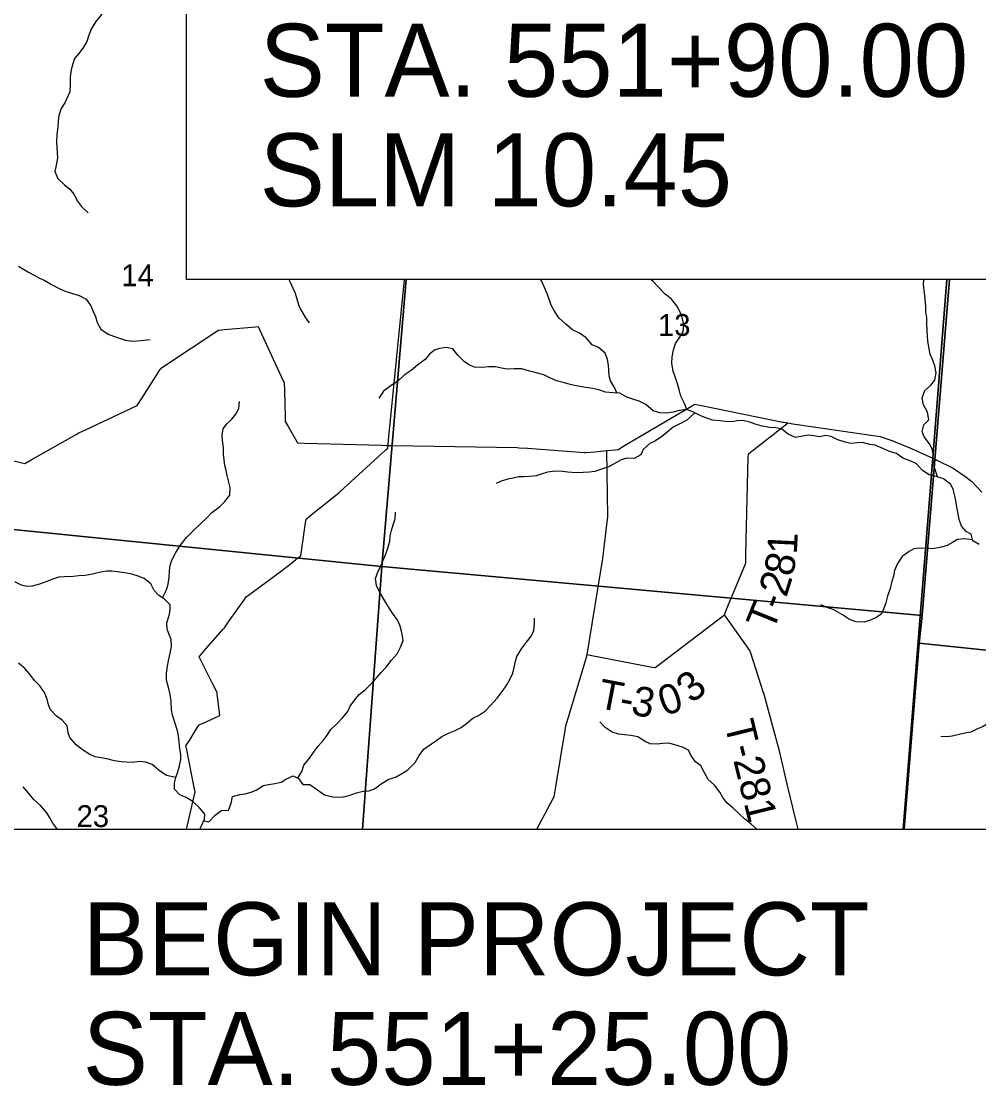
# Model space of a CAD drawing. Extents: x 0 to 34, y 0 to 22.
# Drawn here: x 24.339 to 26.174, y 16.062 to 18.118 of the extents above; entities that cross this region are included whole.
import ezdxf

# ---------------------------------------------------------------- set-up
doc = ezdxf.new("R2010")
doc.units = 0
for name, color, linetype in [('GM_X_Corporation', 7, 'Continuous'), ('GM_X_County_Road', 7, 'Continuous'), ('GM_X_Minor_River', 7, 'Continuous'), ('GM_X_Section_Text', 7, 'Continuous'), ('GM_X_Township_Road', 7, 'Continuous'), ('GM_X_Township_Road_Text', 7, 'Continuous'), ('SH_Data', 7, 'Continuous'), ('SH_Text', 7, 'Continuous')]:
    doc.layers.add(name, color=color, linetype=linetype)

msp = doc.modelspace()

# ---------------------------------------------------------------- linework, layer by layer
at = {"layer": 'GM_X_Corporation'}
for points in [[(25.0768, 17.6235), (25.0299, 17.0732), (24.0111, 17.1749), (24.0929, 18.2038), (24.656, 18.1575)], [(26.3421, 17.8905), (26.9688, 17.8482), (27.1442, 17.8319), (27.1132, 17.3107), (27.1145, 16.8163), (26.06, 16.9257), (26.0658, 16.9791), (26.1183, 17.6235)], [(26.1183, 17.6235), (26.0658, 16.9791), (25.0299, 17.0732), (25.0768, 17.6235)], [(26.1133, 17.6235), (26.0862, 17.2814), (26.0298, 16.5691)], [(26.0298, 16.5691), (26.0862, 17.2814), (26.1133, 17.6235)], [(24.3169, 16.1005), (23.9154, 16.1379), (24.0111, 17.1749), (25.0299, 17.0732), (24.993, 16.5691)], [(24.993, 16.5691), (25.0299, 17.0732), (26.0658, 16.9791), (26.06, 16.9257), (26.0314, 16.5691)], [(26.0314, 16.5691), (26.06, 16.9257), (27.1145, 16.8163), (27.112, 15.7689), (26.1924, 15.8415)]]:
    msp.add_lwpolyline(points, dxfattribs=at)
at = {"layer": 'GM_X_County_Road'}
msp.add_lwpolyline([(24.6557, 16.5691), (24.6569, 16.5743), (24.6703, 16.6329), (24.6721, 16.6408), (24.6698, 16.6525), (24.6562, 16.7213), (24.6547, 16.729), (24.6612, 16.7394), (24.677, 16.7649), (24.6797, 16.7692), (24.6933, 16.7754), (24.7116, 16.7837), (24.7199, 16.7875), (24.7185, 16.7983), (24.7147, 16.8281), (24.7142, 16.8315), (24.7068, 16.8463), (24.6798, 16.9), (24.6928, 16.9151), (24.7259, 16.9527), (24.7283, 16.9553), (24.7378, 16.9688), (24.7668, 17.0096), (24.7704, 17.0146), (24.7816, 17.0229), (24.838, 17.0646), (24.8413, 17.067), (24.8538, 17.0769), (24.8694, 17.0894), (24.8747, 17.0936), (24.8766, 17.1068), (24.8839, 17.1564), (24.8849, 17.1639), (24.8946, 17.1717), (24.9416, 17.2093), (24.9475, 17.214), (24.9567, 17.2224), (25.0381, 17.2967), (25.0416, 17.2999), (25.042, 17.3052), (25.0429, 17.3151), (25.0736, 17.6235)], dxfattribs=at)
at = {"layer": 'GM_X_Minor_River'}
for points in [[(24.547, 18.2577), (24.5353, 18.2481), (24.5356, 18.2375), (24.5378, 18.2261), (24.54, 18.2132), (24.5391, 18.2003), (24.5345, 18.1889), (24.5227, 18.1742), (24.5162, 18.164), (24.5047, 18.1497), (24.4971, 18.1395), (24.491, 18.1289), (24.4822, 18.1176), (24.4734, 18.1044), (24.4684, 18.0919), (24.4645, 18.0794), (24.458, 18.0688), (24.4496, 18.0567), (24.4412, 18.0466), (24.4381, 18.0367), (24.4346, 18.025), (24.4327, 18.0117), (24.4326, 17.9984), (24.4318, 17.983)], [(24.4318, 17.983), (24.4226, 17.9616), (24.4157, 17.9511), (24.4111, 17.9378), (24.41, 17.9276), (24.4092, 17.9158), (24.4072, 17.9014), (24.4064, 17.887), (24.4071, 17.8764), (24.4078, 17.8665), (24.4086, 17.8559), (24.4059, 17.8427), (24.4032, 17.8302), (24.4088, 17.8169), (24.422, 17.8047), (24.4318, 17.7967), (24.4397, 17.7868), (24.4465, 17.7735), (24.4547, 17.7629), (24.4672, 17.7511)], [(24.3336, 17.6485), (24.3529, 17.637), (24.3638, 17.6313), (24.374, 17.626), (24.3839, 17.621), (24.3967, 17.6134), (24.4126, 17.6054), (24.4231, 17.6011), (24.4371, 17.5965), (24.45, 17.5927), (24.4636, 17.5854), (24.4722, 17.5729), (24.4771, 17.5619), (24.4812, 17.552), (24.4846, 17.5406), (24.4917, 17.5281), (24.5053, 17.5182), (24.5155, 17.5147), (24.5253, 17.5113), (24.5385, 17.5067), (24.551, 17.5051), (24.5609, 17.5059), (24.5858, 17.508)], [(24.852, 17.6235), (24.8545, 17.6181), (24.8597, 17.6067), (24.8638, 17.5972), (24.8679, 17.5836), (24.8717, 17.5714), (24.8769, 17.5619), (24.8841, 17.5498), (24.8909, 17.5403)], [(25.4806, 17.4056), (25.476, 17.4161), (25.4688, 17.4286), (25.4659, 17.4385), (25.4651, 17.4491), (25.4648, 17.459), (25.4626, 17.47), (25.4581, 17.4817), (25.4456, 17.4928), (25.4332, 17.4981), (25.4219, 17.5114), (25.4094, 17.5202), (25.3954, 17.5267), (25.3826, 17.5377), (25.3694, 17.5499), (25.3608, 17.5636), (25.3548, 17.5742), (25.348, 17.5947), (25.342, 17.6076), (25.336, 17.6209), (25.3346, 17.6235)], [(25.6147, 17.3739), (25.6106, 17.3857), (25.6034, 17.3993), (25.6008, 17.41), (25.5967, 17.4232), (25.593, 17.4346), (25.5888, 17.4475), (25.5862, 17.4623), (25.587, 17.4748), (25.5894, 17.4881), (25.5928, 17.5006), (25.6, 17.5104), (25.608, 17.5229), (25.6092, 17.5365), (25.6062, 17.5506), (25.6021, 17.5604), (25.5957, 17.5726), (25.5852, 17.5855), (25.5727, 17.5954), (25.5596, 17.6091), (25.5505, 17.6194), (25.5456, 17.6235)], [(26.0955, 17.2447), (26.0894, 17.263), (26.0868, 17.2766), (26.0872, 17.2891), (26.0854, 17.2986), (26.0801, 17.3081), (26.0699, 17.3214), (26.0662, 17.332), (26.0689, 17.3445), (26.0788, 17.354), (26.0765, 17.3688), (26.0687, 17.3828), (26.0661, 17.3961), (26.071, 17.4105), (26.0828, 17.4203), (26.0904, 17.4301), (26.0927, 17.4445), (26.0905, 17.4578), (26.0856, 17.4699), (26.0815, 17.4802), (26.0793, 17.4901), (26.0771, 17.5049), (26.0763, 17.5147), (26.0756, 17.5249), (26.0749, 17.5397), (26.0746, 17.5504), (26.0731, 17.5606), (26.0728, 17.5716), (26.0717, 17.586), (26.0702, 17.5974), (26.0688, 17.6129), (26.0691, 17.6235)], [(25.4737, 17.4062), (25.4589, 17.4074), (25.448, 17.4113), (25.4344, 17.414), (25.4215, 17.4159), (25.4064, 17.4186), (25.3935, 17.4213), (25.3777, 17.4259), (25.3648, 17.429), (25.352, 17.4344), (25.341, 17.4401), (25.3263, 17.4443), (25.3134, 17.4474), (25.2983, 17.452), (25.284, 17.4517), (25.2707, 17.4513), (25.2597, 17.4533), (25.248, 17.456), (25.2355, 17.4556), (25.2219, 17.4542), (25.2079, 17.455), (25.1981, 17.4592), (25.1883, 17.466), (25.1759, 17.4782), (25.1661, 17.4904), (25.1543, 17.4927), (25.1407, 17.4912), (25.1309, 17.4878), (25.1214, 17.4799), (25.1134, 17.4701), (25.099, 17.4595), (25.0865, 17.4486), (25.0728, 17.4399), (25.0603, 17.4278), (25.0478, 17.4199), (25.0334, 17.409), (25.0246, 17.3957)], [(26.1755, 17.1152), (26.163, 17.1224), (26.16, 17.1349), (26.1502, 17.1403), (26.1416, 17.1502), (26.1371, 17.1631), (26.1348, 17.1741), (26.1326, 17.1866), (26.1304, 17.1987), (26.1285, 17.2082), (26.1252, 17.2211), (26.1203, 17.2306), (26.1067, 17.2413), (26.0927, 17.2455), (26.0791, 17.2486), (26.0663, 17.257), (26.0542, 17.2707), (26.041, 17.276), (26.0286, 17.2806), (26.0165, 17.2898), (26.0051, 17.2928), (25.9904, 17.2993), (25.9761, 17.3055), (25.9659, 17.307), (25.9519, 17.3109), (25.9417, 17.3101), (25.9288, 17.3087), (25.9186, 17.3114), (25.9046, 17.3156), (25.8914, 17.3225), (25.8812, 17.3244), (25.8683, 17.3214), (25.8585, 17.3233), (25.8483, 17.3245), (25.8365, 17.323), (25.8233, 17.3204), (25.8089, 17.3269), (25.7969, 17.3365), (25.7855, 17.3388), (25.7742, 17.3392), (25.7594, 17.3419), (25.7458, 17.3461), (25.7353, 17.3496), (25.722, 17.353), (25.7122, 17.3523), (25.7008, 17.3501), (25.6884, 17.3509), (25.6785, 17.3524), (25.6641, 17.3536), (25.6532, 17.3571), (25.643, 17.3613), (25.6286, 17.3682), (25.6147, 17.3739), (25.6003, 17.372), (25.5889, 17.3691), (25.5761, 17.3668), (25.5628, 17.3676), (25.5503, 17.3715), (25.5364, 17.3837), (25.5232, 17.3901), (25.5134, 17.3932), (25.5001, 17.3978), (25.4862, 17.4051), (25.4737, 17.4062)], [(24.6098, 17.0129), (24.6166, 17.0269), (24.6197, 17.0367), (24.6224, 17.0515), (24.6232, 17.0652), (24.6243, 17.0746), (24.6278, 17.0852), (24.6346, 17.0988), (24.6438, 17.1132), (24.6559, 17.1287), (24.6685, 17.1412), (24.6829, 17.1551), (24.695, 17.1665), (24.7041, 17.1763), (24.7189, 17.1876), (24.7292, 17.1974), (24.7391, 17.2099), (24.7395, 17.2247), (24.7365, 17.2372), (24.7339, 17.2474), (24.7317, 17.2569), (24.7291, 17.2668), (24.7269, 17.288), (24.7269, 17.3013), (24.7247, 17.3146), (24.7244, 17.3244), (24.7259, 17.3366), (24.7328, 17.3464), (24.7423, 17.3551), (24.7502, 17.3653), (24.756, 17.3759), (24.7575, 17.3891)], [(25.6304, 17.3673), (25.6146, 17.3538), (25.6013, 17.3466), (25.5884, 17.3399), (25.5767, 17.3297), (25.5664, 17.3214), (25.5535, 17.3131), (25.5437, 17.3086), (25.5312, 17.2972), (25.5266, 17.287), (25.5137, 17.2799), (25.5001, 17.2807), (25.4891, 17.2773), (25.4755, 17.2698), (25.4645, 17.2641), (25.4512, 17.2596), (25.4387, 17.2551), (25.4285, 17.2536), (25.4164, 17.2529), (25.4024, 17.2526), (25.3865, 17.2538), (25.3763, 17.2553), (25.3627, 17.2558), (25.3479, 17.2536), (25.3358, 17.2502), (25.3259, 17.2468), (25.3123, 17.2453), (25.3021, 17.245), (25.2923, 17.245), (25.282, 17.2424), (25.2714, 17.2402), (25.2589, 17.2364), (25.2491, 17.2323)], [(24.8691, 16.6672), (24.8771, 16.6798), (24.8809, 16.692), (24.8912, 16.7052), (24.9003, 16.7184), (24.9083, 16.7283), (24.9174, 16.7392), (24.9254, 16.7498), (24.9326, 16.7604), (24.9448, 16.7717), (24.955, 16.783), (24.9649, 16.7951), (24.9695, 16.805), (24.9786, 16.8171), (24.987, 16.8273), (24.998, 16.8363), (25.0086, 16.8465), (25.0204, 16.8598), (25.0291, 16.8696), (25.0382, 16.8802), (25.0485, 16.8934), (25.0595, 16.9055), (25.066, 16.918), (25.0709, 16.9308), (25.0683, 16.9464), (25.0654, 16.9585), (25.0609, 16.9692), (25.0503, 16.9832), (25.0417, 16.9973), (25.0342, 17.0102), (25.0259, 17.0242), (25.0199, 17.0368), (25.018, 17.0501), (25.023, 17.0637), (25.028, 17.0735), (25.0329, 17.0849), (25.0375, 17.0955), (25.0417, 17.108), (25.0452, 17.1216), (25.0463, 17.1318), (25.049, 17.1421), (25.0521, 17.1527), (25.0555, 17.1644), (25.0563, 17.1769)], [(26.1627, 17.1239), (26.1464, 17.1263), (26.1339, 17.1244), (26.1244, 17.1192), (26.1138, 17.1135), (26.1028, 17.1098), (26.0862, 17.1068), (26.076, 17.1072), (26.0612, 17.108), (26.0502, 17.1065), (26.0408, 17.102), (26.0279, 17.0918), (26.0184, 17.0786), (26.013, 17.0654), (26.0107, 17.0544), (26.008, 17.0445), (26.0046, 17.0305), (25.9996, 17.0161), (25.9965, 17.0033), (25.9923, 16.9923), (25.9877, 16.9821), (25.9783, 16.9753), (25.965, 16.9696), (25.9548, 16.9663), (25.9396, 16.9671), (25.9268, 16.9713), (25.9132, 16.9805), (25.8955, 16.9904), (25.8849, 16.9934), (25.872, 16.9992)], [(24.6813, 16.5691), (24.6838, 16.5744), (24.6902, 16.5884), (24.6907, 16.5979), (24.6809, 16.6104), (24.6677, 16.6226), (24.6552, 16.6303), (24.6431, 16.6352), (24.633, 16.6459), (24.633, 16.6584), (24.6353, 16.6682), (24.6391, 16.6792), (24.6426, 16.6909), (24.6449, 16.7027), (24.6446, 16.7125), (24.6431, 16.7232), (24.6416, 16.7361), (24.6401, 16.7482), (24.6387, 16.7581), (24.6331, 16.774), (24.6289, 16.7877), (24.6267, 16.7983), (24.6264, 16.8138), (24.6242, 16.8275), (24.6216, 16.8381), (24.6175, 16.8552), (24.6171, 16.8684), (24.6195, 16.8817), (24.621, 16.8923), (24.6245, 16.9067), (24.6272, 16.9196), (24.6261, 16.9328), (24.6223, 16.9423), (24.6186, 16.9526), (24.6182, 16.9651), (24.6228, 16.9791), (24.6244, 16.9886), (24.6244, 16.9996), (24.6127, 17.011), (24.6029, 17.0175), (24.5939, 17.027), (24.5871, 17.0399), (24.5743, 17.0498), (24.563, 17.0544), (24.5509, 17.0582), (24.5376, 17.0605), (24.5233, 17.0625), (24.5127, 17.0637), (24.5025, 17.0637), (24.4881, 17.0615), (24.4756, 17.0581), (24.4612, 17.0555), (24.4495, 17.0552), (24.4385, 17.0537)], [(24.4385, 17.0537), (24.4219, 17.0534), (24.4105, 17.0527), (24.3995, 17.0486), (24.3882, 17.044), (24.3741, 17.0388), (24.3601, 17.0354), (24.3499, 17.0343), (24.3393, 17.0374), (24.3269, 17.0435)], [(24.6887, 16.5851), (24.6986, 16.5835), (24.7107, 16.5963), (24.7236, 16.6057), (24.7361, 16.6053), (24.7411, 16.6193), (24.7437, 16.6322), (24.7581, 16.6356), (24.768, 16.637), (24.7797, 16.64), (24.7903, 16.6449), (24.8025, 16.6528), (24.8131, 16.6551), (24.8252, 16.6569), (24.8369, 16.6595), (24.8464, 16.6652), (24.8604, 16.6719), (24.8702, 16.6666), (24.8789, 16.6552), (24.8921, 16.6548), (24.9068, 16.6449), (24.92, 16.6353), (24.9355, 16.6315), (24.9533, 16.6307), (24.9677, 16.6336), (24.9817, 16.6393), (24.9942, 16.6423), (25.0056, 16.643), (25.0162, 16.6464), (25.0291, 16.6562), (25.0423, 16.6648), (25.0579, 16.6697), (25.0696, 16.6765), (25.0799, 16.6829), (25.0939, 16.6972), (25.1015, 16.7105), (25.1106, 16.7226), (25.1254, 16.7331), (25.1357, 16.7399), (25.1455, 16.7467), (25.1577, 16.7535), (25.1706, 16.7588), (25.1823, 16.764), (25.1922, 16.7719), (25.2043, 16.7821), (25.2153, 16.787), (25.2286, 16.7961), (25.2384, 16.8067), (25.251, 16.8206), (25.2628, 16.8358), (25.2696, 16.846), (25.2757, 16.8566), (25.2814, 16.8687), (25.2841, 16.8793), (25.2857, 16.8891), (25.2887, 16.9005), (25.2979, 16.9148), (25.3074, 16.9281), (25.3169, 16.9402), (25.3218, 16.95), (25.3226, 16.9637), (25.323, 16.9739)], [(24.6353, 16.6682), (24.6175, 16.6725), (24.6036, 16.6816), (24.59, 16.693), (24.5772, 16.6976), (24.5654, 16.6988), (24.5522, 16.6973), (24.5401, 16.6978), (24.5303, 16.6986), (24.5174, 16.7001), (24.5027, 16.704), (24.4921, 16.7059), (24.4804, 16.7082), (24.4702, 16.7128), (24.4566, 16.7216), (24.4445, 16.7311), (24.4321, 16.7448), (24.4287, 16.7543), (24.4269, 16.7676), (24.4171, 16.7786), (24.4065, 16.7862), (24.3952, 16.7984), (24.3914, 16.8079), (24.3888, 16.8185), (24.3836, 16.8314), (24.3746, 16.8443), (24.3651, 16.8538), (24.3538, 16.8675), (24.3459, 16.8774), (24.3335, 16.8873)], [(26.37, 16.856), (26.3588, 16.8571), (26.3448, 16.8545), (26.3319, 16.8492), (26.3182, 16.8425), (26.3046, 16.8361), (26.2947, 16.8308), (26.2826, 16.824), (26.2674, 16.8154), (26.2568, 16.8086), (26.247, 16.8022), (26.2345, 16.7958), (26.2204, 16.7879), (26.2102, 16.7837), (26.1969, 16.7743), (26.1814, 16.7653), (26.1719, 16.7615), (26.159, 16.7555), (26.148, 16.7533), (26.1234, 16.7477), (26.1132, 16.7466), (26.1019, 16.747)], [(25.749, 16.5691), (25.7381, 16.5789), (25.7253, 16.5892), (25.7147, 16.5991), (25.7034, 16.6094), (25.6913, 16.6196), (25.6838, 16.6299), (25.6782, 16.6402), (25.6676, 16.6535), (25.6559, 16.6645), (25.648, 16.6789), (25.6417, 16.6907), (25.6315, 16.6987), (25.6228, 16.7112), (25.6183, 16.7207), (25.6066, 16.7265), (25.5919, 16.7311), (25.5802, 16.7341), (25.568, 16.7338), (25.5578, 16.7323), (25.5446, 16.7331), (25.5348, 16.7377), (25.5208, 16.7465), (25.5072, 16.7488), (25.4951, 16.7504), (25.4841, 16.7516), (25.472, 16.7554), (25.4585, 16.7642), (25.4479, 16.7748)], [(24.4082, 16.5691), (24.4072, 16.5705), (24.3993, 16.5808), (24.3937, 16.5911), (24.3877, 16.6009), (24.3767, 16.6142), (24.3635, 16.6257), (24.3428, 16.6508)]]:
    msp.add_lwpolyline(points, dxfattribs=at)
at = {"layer": 'GM_X_Township_Road'}
msp.add_line((25.8281, 16.5691), (25.8236, 16.5875), dxfattribs=at)
for points in [[(24.2955, 17.2826), (24.34, 17.2716), (24.3455, 17.2702), (24.3578, 17.2772), (24.4444, 17.3262), (24.4495, 17.3291), (24.4621, 17.3351), (24.5611, 17.3817), (24.5719, 17.3983), (24.6042, 17.4485), (24.6073, 17.4533), (24.6191, 17.4612), (24.7102, 17.5218), (24.7169, 17.5262), (24.7286, 17.5273), (24.7881, 17.5327), (24.7928, 17.5331), (24.7992, 17.5193), (24.8412, 17.4292), (24.8428, 17.4256), (24.8433, 17.4097), (24.8448, 17.36), (24.8451, 17.3511), (24.8505, 17.3415), (24.8652, 17.3156), (24.8683, 17.3101), (24.8819, 17.3097), (25.031, 17.3054), (25.0386, 17.3052), (25.042, 17.3052), (25.0509, 17.305), (25.2895, 17.3008), (25.2935, 17.3007), (25.3093, 17.2995), (25.4184, 17.2915), (25.4213, 17.2912), (25.4382, 17.2929), (25.4613, 17.2952), (25.4777, 17.2968), (25.4832, 17.2973), (25.4956, 17.3047), (25.624, 17.3806), (25.6296, 17.384), (25.6427, 17.3813), (25.7986, 17.3499), (25.8011, 17.3494), (25.8084, 17.3481), (25.8182, 17.3463), (25.9856, 17.322), (26.0095, 17.3139)], [(25.6877, 16.9822), (25.6918, 16.9922), (25.713, 17.0439), (25.7271, 17.0783), (25.7278, 17.0801), (25.7282, 17.0967), (25.7326, 17.2826), (25.7328, 17.289), (25.7424, 17.2965), (25.801, 17.3423), (25.8084, 17.3481)], [(26.0095, 17.3139), (26.0142, 17.3122), (26.0425, 17.3005), (26.0864, 17.2808), (26.0908, 17.2787)], [(25.424, 16.9042), (25.4539, 17.0882), (25.4634, 17.1687), (25.4613, 17.2952)], [(26.0908, 17.2787), (26.0943, 17.2769), (26.1256, 17.2612), (26.1476, 17.2459), (26.1609, 17.2361), (26.1805, 17.2153)], [(25.424, 16.9042), (25.4329, 16.9025), (25.5487, 16.8802), (25.5541, 16.8791), (25.5641, 16.8868), (25.6796, 16.9747), (25.6869, 16.9802)], [(25.8236, 16.5875), (25.807, 16.6557), (25.7923, 16.7196), (25.7899, 16.7286), (25.7629, 16.8273), (25.7608, 16.8347), (25.7575, 16.845), (25.7375, 16.907), (25.7358, 16.9122), (25.7282, 16.9228), (25.6901, 16.9757), (25.6869, 16.9802), (25.6877, 16.9822)], [(25.3275, 16.5691), (25.3588, 16.628), (25.3606, 16.6314), (25.3632, 16.6469), (25.3823, 16.7631), (25.383, 16.7674), (25.3874, 16.782), (25.4212, 16.8947), (25.424, 16.9042)]]:
    msp.add_lwpolyline(points, dxfattribs=at)
at = {"layer": 'SH_Data'}
for points in [[(24.656, 18.4635), (26.3421, 18.4635), (26.3421, 17.6235), (24.656, 17.6235)], [(24.3169, 16.5691), (26.1924, 16.5691), (26.1924, 15.7291), (24.3169, 15.7291)]]:
    msp.add_lwpolyline(points, close=True, dxfattribs=at)

# ---------------------------------------------------------------- texts
at = {"layer": 'GM_X_Section_Text'}
for s, p in [('14', (24.5308, 17.6104)), ('13', (25.5596, 17.5151)), ('23', (24.445, 16.5734))]:
    msp.add_text(s, height=0.04186, rotation=0, dxfattribs=at).set_placement(p)
at = {"layer": 'GM_X_Township_Road_Text'}
for s, height, rotation, p in [('1', 0.0568, 87.2046, (25.8257, 17.0955)), ('8', 0.0568, 78.5524, (25.8176, 17.0519)), ('2', 0.0568, 72.6804, (25.8056, 17.0123)), ('T', 0.0568, 68.0569, (25.7797, 16.9464)), ('-', 0.0568, 69.1535, (25.796, 16.9869)), ('T', 0.0568, 349.104, (25.4415, 16.8022)), ('3', 0.0568, 40.9649, (25.6251, 16.8086)), ('3', 0.0568, 349.1052, (25.5058, 16.7898)), ('0', 0.0568, 19.1006, (25.5719, 16.7855)), ('-', 0.0568, 349.1042, (25.4831, 16.7942)), ('T-281', 0.05682, 283.8383, (25.6865, 16.7714))]:
    msp.add_text(s, height=height, rotation=rotation, dxfattribs=at).set_placement(p)
at = {"layer": 'SH_Text'}
for s, p in [('STA. 551+90.00', (24.796, 17.9735)), ('SLM 10.45', (24.796, 17.7635)), ('BEGIN PROJECT', (24.4569, 16.2891)), ('STA. 551+25.00', (24.4569, 16.0791))]:
    msp.add_text(s, height=0.14, dxfattribs=at).set_placement(p)

doc.saveas('drawing.dxf')
